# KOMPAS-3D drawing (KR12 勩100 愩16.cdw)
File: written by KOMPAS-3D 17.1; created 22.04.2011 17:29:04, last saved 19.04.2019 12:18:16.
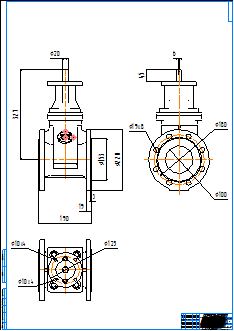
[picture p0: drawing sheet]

Title block, sheet 1: name: KR12 Ду100 Ру16; material: Внимание! Данный продукт является объектом авторского права ООО «Торговый Дом АДЛ». / Запрещается изменение, копирование, распространение / (в том числе путем копирования на другие сайты и ресурсы в Интернете) / или любое иное использование информации и объектов без предварительного / согласия правообладателя (ООО «Торговый Дом АДЛ»).; scale: 1:1; sheets: 1; organisation: ООО "Торговый дом АДЛ"; sheet format: A0; stored path: \\adlc.lan\data\АДЛ_ПКД\3D-модели\ADL production\Клиновые задвижки серии KR ГРАНАР\Клиновые задвижки KR12\KOMPAS 2D\KR12 Ду100 Ру16.cdw

Views: Спереди 4, Проекционный вид 5, Проекционный вид 6
Dimensions and other numbers on the sheet: 153; 220; 190; 19; 3; 327; 20; 125; 10; 6; 100; 180; 45; 1:1; 1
